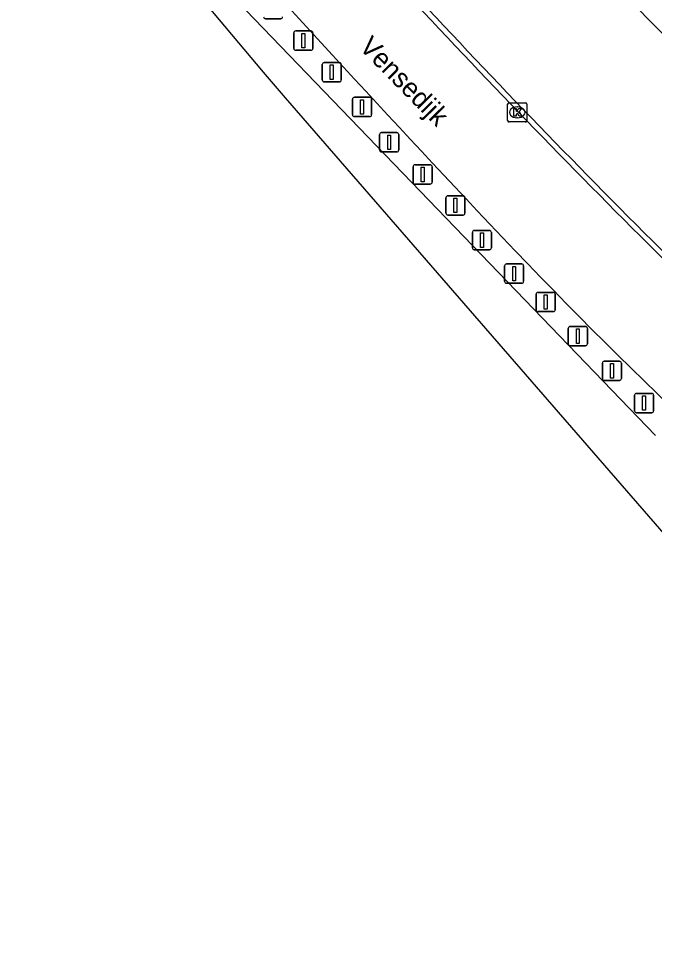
# Model space of a CAD drawing. Extents: x 156061 to 157804, y 383451 to 385640.
# Drawn here: x 156085.13 to 156118.12, y 385284.11 to 385332.59 of the extents above; entities that cross this region are included whole.
import ezdxf

# ---------------------------------------------------------------- set-up
doc = ezdxf.new("R2010")
doc.units = 0
for name, color, linetype in [('IMGEO_Afsluitpaal', 7, 'Continuous'), ('IMGEO_Berm_groen', 7, 'Continuous'), ('IMGEO_Groenvoorziening', 7, 'Continuous'), ('IMGEO_Kolk', 7, 'Continuous'), ('IMGEO_Openbare_ruimte_label', 7, 'Continuous'), ('IMGEO_Rijbaan_lokaal_gesloten', 7, 'Continuous'), ('IMGEO_Rijbaan_lokaal_open', 7, 'Continuous'), ('IMGEO_Waterloop', 7, 'Continuous')]:
    doc.layers.add(name, color=color, linetype=linetype)

msp = doc.modelspace()

# ---------------------------------------------------------------- linework, layer by layer
at = {"layer": 'IMGEO_Afsluitpaal'}
for p, q in [((156098.728, 385332.585), (156097.938, 385332.585)), ((156097.938, 385332.585), (156098.728, 385332.585)), ((156099.41, 385331.048), (156099.41, 385331.848)), ((156099.41, 385331.848), (156099.41, 385331.048)), ((156099.51, 385331.948), (156100.3, 385331.948)), ((156100.3, 385331.948), (156099.51, 385331.948)), ((156100.4, 385331.848), (156100.4, 385331.048)), ((156100.4, 385331.048), (156100.4, 385331.848)), ((156100.3, 385330.948), (156099.51, 385330.948)), ((156099.51, 385330.948), (156100.3, 385330.948)), ((156100.884, 385329.41), (156100.884, 385330.21)), ((156100.884, 385330.21), (156100.884, 385329.41)), ((156100.984, 385330.31), (156101.774, 385330.31)), ((156101.774, 385330.31), (156100.984, 385330.31)), ((156101.874, 385330.21), (156101.874, 385329.41)), ((156101.874, 385329.41), (156101.874, 385330.21)), ((156101.774, 385329.31), (156100.984, 385329.31)), ((156100.984, 385329.31), (156101.774, 385329.31)), ((156102.455, 385327.609), (156102.455, 385328.409)), ((156102.455, 385328.409), (156102.455, 385327.609)), ((156102.555, 385328.509), (156103.345, 385328.509)), ((156103.345, 385328.509), (156102.555, 385328.509)), ((156103.445, 385328.409), (156103.445, 385327.609)), ((156103.445, 385327.609), (156103.445, 385328.409)), ((156103.345, 385327.509), (156102.555, 385327.509)), ((156102.555, 385327.509), (156103.345, 385327.509)), ((156103.863, 385325.776), (156103.863, 385326.576)), ((156103.863, 385326.576), (156103.863, 385325.776)), ((156103.963, 385326.676), (156104.753, 385326.676)), ((156104.753, 385326.676), (156103.963, 385326.676)), ((156104.853, 385326.576), (156104.853, 385325.776)), ((156104.853, 385325.776), (156104.853, 385326.576)), ((156104.753, 385325.676), (156103.963, 385325.676)), ((156103.963, 385325.676), (156104.753, 385325.676)), ((156105.599, 385324.106), (156105.599, 385324.906)), ((156105.599, 385324.906), (156105.599, 385324.106)), ((156105.699, 385325.006), (156106.489, 385325.006)), ((156106.489, 385325.006), (156105.699, 385325.006)), ((156106.589, 385324.906), (156106.589, 385324.106)), ((156106.589, 385324.106), (156106.589, 385324.906)), ((156106.489, 385324.006), (156105.699, 385324.006)), ((156105.699, 385324.006), (156106.489, 385324.006)), ((156107.402, 385323.401), (156108.192, 385323.401)), ((156108.192, 385323.401), (156107.402, 385323.401)), ((156107.302, 385322.501), (156107.302, 385323.301)), ((156107.302, 385323.301), (156107.302, 385322.501)), ((156108.292, 385323.301), (156108.292, 385322.501)), ((156108.292, 385322.501), (156108.292, 385323.301)), ((156108.192, 385322.401), (156107.402, 385322.401)), ((156107.402, 385322.401), (156108.192, 385322.401)), ((156108.677, 385320.7), (156108.677, 385321.5)), ((156108.677, 385321.5), (156108.677, 385320.7)), ((156108.777, 385321.6), (156109.567, 385321.6)), ((156109.567, 385321.6), (156108.777, 385321.6)), ((156109.667, 385321.5), (156109.667, 385320.7)), ((156109.667, 385320.7), (156109.667, 385321.5)), ((156109.567, 385320.6), (156108.777, 385320.6)), ((156108.777, 385320.6), (156109.567, 385320.6)), ((156110.347, 385318.965), (156110.347, 385319.765)), ((156110.347, 385319.765), (156110.347, 385318.965)), ((156110.447, 385319.865), (156111.237, 385319.865)), ((156111.237, 385319.865), (156110.447, 385319.865)), ((156111.337, 385319.765), (156111.337, 385318.965)), ((156111.337, 385318.965), (156111.337, 385319.765)), ((156111.237, 385318.865), (156110.447, 385318.865)), ((156110.447, 385318.865), (156111.237, 385318.865)), ((156111.984, 385317.491), (156111.984, 385318.291)), ((156111.984, 385318.291), (156111.984, 385317.491)), ((156112.084, 385318.391), (156112.874, 385318.391)), ((156112.874, 385318.391), (156112.084, 385318.391)), ((156112.974, 385318.291), (156112.974, 385317.491)), ((156112.974, 385317.491), (156112.974, 385318.291)), ((156112.874, 385317.391), (156112.084, 385317.391)), ((156112.084, 385317.391), (156112.874, 385317.391)), ((156113.754, 385316.623), (156114.544, 385316.623)), ((156114.544, 385316.623), (156113.754, 385316.623)), ((156113.654, 385315.723), (156113.654, 385316.523)), ((156113.654, 385316.523), (156113.654, 385315.723)), ((156114.644, 385316.523), (156114.644, 385315.723)), ((156114.644, 385315.723), (156114.644, 385316.523)), ((156114.544, 385315.623), (156113.754, 385315.623)), ((156113.754, 385315.623), (156114.544, 385315.623)), ((156115.422, 385313.922), (156115.422, 385314.722)), ((156115.422, 385314.722), (156115.422, 385313.922)), ((156115.522, 385314.822), (156116.312, 385314.822)), ((156116.312, 385314.822), (156115.522, 385314.822)), ((156116.412, 385314.722), (156116.412, 385313.922)), ((156116.412, 385313.922), (156116.412, 385314.722)), ((156116.312, 385313.822), (156115.522, 385313.822)), ((156115.522, 385313.822), (156116.312, 385313.822)), ((156117.092, 385312.252), (156117.092, 385313.052)), ((156117.092, 385313.052), (156117.092, 385312.252)), ((156117.192, 385313.152), (156117.982, 385313.152)), ((156117.982, 385313.152), (156117.192, 385313.152)), ((156118.082, 385313.052), (156118.082, 385312.252)), ((156118.082, 385312.252), (156118.082, 385313.052)), ((156117.982, 385312.152), (156117.192, 385312.152)), ((156117.192, 385312.152), (156117.982, 385312.152))]:
    msp.add_line(p, q, dxfattribs=at)
for points in [[(156099.83, 385331.823), (156099.98, 385331.823), (156099.98, 385331.073), (156099.83, 385331.073), (156099.83, 385331.823)], [(156101.304, 385330.185), (156101.454, 385330.185), (156101.454, 385329.435), (156101.304, 385329.435), (156101.304, 385330.185)], [(156102.875, 385328.384), (156103.025, 385328.384), (156103.025, 385327.634), (156102.875, 385327.634), (156102.875, 385328.384)], [(156104.283, 385326.551), (156104.433, 385326.551), (156104.433, 385325.801), (156104.283, 385325.801), (156104.283, 385326.551)], [(156106.019, 385324.881), (156106.169, 385324.881), (156106.169, 385324.131), (156106.019, 385324.131), (156106.019, 385324.881)], [(156107.722, 385323.276), (156107.872, 385323.276), (156107.872, 385322.526), (156107.722, 385322.526), (156107.722, 385323.276)], [(156109.097, 385321.475), (156109.247, 385321.475), (156109.247, 385320.725), (156109.097, 385320.725), (156109.097, 385321.475)], [(156110.767, 385319.74), (156110.917, 385319.74), (156110.917, 385318.99), (156110.767, 385318.99), (156110.767, 385319.74)], [(156112.404, 385318.266), (156112.554, 385318.266), (156112.554, 385317.516), (156112.404, 385317.516), (156112.404, 385318.266)], [(156114.074, 385316.498), (156114.224, 385316.498), (156114.224, 385315.748), (156114.074, 385315.748), (156114.074, 385316.498)], [(156115.842, 385314.697), (156115.992, 385314.697), (156115.992, 385313.947), (156115.842, 385313.947), (156115.842, 385314.697)], [(156117.512, 385313.027), (156117.662, 385313.027), (156117.662, 385312.277), (156117.512, 385312.277), (156117.512, 385313.027)]]:
    msp.add_lwpolyline(points, dxfattribs=at)
for centre, start, end in [((156097.938, 385332.685), 180, 270), ((156097.938, 385332.685), 180, 270), ((156098.728, 385332.685), 270, 0), ((156098.728, 385332.685), 270, 0), ((156099.51, 385331.848), 90, 180), ((156099.51, 385331.848), 90, 180), ((156100.3, 385331.848), 0, 90), ((156100.3, 385331.848), 360, 90), ((156099.51, 385331.048), 180, 270), ((156099.51, 385331.048), 180, 270), ((156100.3, 385331.048), 270, 0), ((156100.3, 385331.048), 270, 0), ((156100.984, 385330.21), 90, 180), ((156100.984, 385330.21), 90, 180), ((156101.774, 385330.21), 0, 90), ((156101.774, 385330.21), 360, 90), ((156100.984, 385329.41), 180, 270), ((156100.984, 385329.41), 180, 270), ((156101.774, 385329.41), 270, 0), ((156101.774, 385329.41), 270, 0), ((156102.555, 385328.409), 90, 180), ((156102.555, 385328.409), 90, 180), ((156103.345, 385328.409), 0, 90), ((156103.345, 385328.409), 360, 90), ((156102.555, 385327.609), 180, 270), ((156102.555, 385327.609), 180, 270), ((156103.345, 385327.609), 270, 0), ((156103.345, 385327.609), 270, 0), ((156103.963, 385326.576), 90, 180), ((156103.963, 385326.576), 90, 180), ((156104.753, 385326.576), 0, 90), ((156104.753, 385326.576), 360, 90), ((156103.963, 385325.776), 180, 270), ((156103.963, 385325.776), 180, 270), ((156104.753, 385325.776), 270, 0), ((156104.753, 385325.776), 270, 0), ((156105.699, 385324.906), 90, 180), ((156105.699, 385324.906), 90, 180), ((156106.489, 385324.906), 0, 90), ((156106.489, 385324.906), 360, 90), ((156105.699, 385324.106), 180, 270), ((156105.699, 385324.106), 180, 270), ((156106.489, 385324.106), 270, 0), ((156106.489, 385324.106), 270, 0), ((156107.402, 385323.301), 90, 180), ((156107.402, 385323.301), 90, 180), ((156108.192, 385323.301), 0, 90), ((156108.192, 385323.301), 360, 90), ((156107.402, 385322.501), 180, 270), ((156107.402, 385322.501), 180, 270), ((156108.192, 385322.501), 270, 0), ((156108.192, 385322.501), 270, 0), ((156108.777, 385321.5), 90, 180), ((156108.777, 385321.5), 90, 180), ((156109.567, 385321.5), 0, 90), ((156109.567, 385321.5), 360, 90), ((156108.777, 385320.7), 180, 270), ((156108.777, 385320.7), 180, 270), ((156109.567, 385320.7), 270, 0), ((156109.567, 385320.7), 270, 0), ((156110.447, 385319.765), 90, 180), ((156110.447, 385319.765), 90, 180), ((156111.237, 385319.765), 0, 90), ((156111.237, 385319.765), 360, 90), ((156110.447, 385318.965), 180, 270), ((156110.447, 385318.965), 180, 270), ((156111.237, 385318.965), 270, 0), ((156111.237, 385318.965), 270, 0), ((156112.084, 385318.291), 90, 180), ((156112.084, 385318.291), 90, 180), ((156112.874, 385318.291), 0, 90), ((156112.874, 385318.291), 360, 90), ((156112.084, 385317.491), 180, 270), ((156112.084, 385317.491), 180, 270), ((156112.874, 385317.491), 270, 0), ((156112.874, 385317.491), 270, 0), ((156113.754, 385316.523), 90, 180), ((156113.754, 385316.523), 90, 180), ((156114.544, 385316.523), 0, 90), ((156114.544, 385316.523), 360, 90), ((156113.754, 385315.723), 180, 270), ((156113.754, 385315.723), 180, 270), ((156114.544, 385315.723), 270, 0), ((156114.544, 385315.723), 270, 0), ((156115.522, 385314.722), 90, 180), ((156115.522, 385314.722), 90, 180), ((156116.312, 385314.722), 0, 90), ((156116.312, 385314.722), 360, 90), ((156115.522, 385313.922), 180, 270), ((156115.522, 385313.922), 180, 270), ((156116.312, 385313.922), 270, 0), ((156116.312, 385313.922), 270, 0), ((156117.192, 385313.052), 90, 180), ((156117.192, 385313.052), 90, 180), ((156117.982, 385313.052), 0, 90), ((156117.982, 385313.052), 360, 90), ((156117.192, 385312.252), 180, 270), ((156117.192, 385312.252), 180, 270), ((156117.982, 385312.252), 270, 0), ((156117.982, 385312.252), 270, 0)]:
    msp.add_arc(centre, 0.1, start, end, dxfattribs=at)
at = {"layer": 'IMGEO_Berm_groen'}
msp.add_lwpolyline([(156118.185, 385310.964), (156091.934, 385338.209), (156086.7, 385344.464)], dxfattribs=at)
at = {"layer": 'IMGEO_Groenvoorziening'}
msp.add_lwpolyline([(156102.695, 385354.328), (156101.165, 385350.479), (156108.949, 385341.526), (156111.805, 385338.65), (156128.476, 385321.756), (156168.153, 385284.113)], dxfattribs=at)
at = {"layer": 'IMGEO_Kolk'}
for p, q in [((156110.58, 385328.228), (156111.432, 385328.228)), ((156110.505, 385327.302), (156110.505, 385328.154)), ((156110.993, 385328.008), (156111.018, 385328.008)), ((156111.506, 385328.154), (156111.506, 385327.302)), ((156111.432, 385327.228), (156110.58, 385327.228)), ((156111.016, 385327.448), (156110.991, 385327.448))]:
    msp.add_line(p, q, dxfattribs=at)
for points in [[(156110.58, 385328.228), (156111.432, 385328.228)], [(156110.505, 385327.302), (156110.505, 385328.154)], [(156110.826, 385327.928), (156110.949, 385327.928), (156110.949, 385327.777), (156111.079, 385327.928), (156111.243, 385327.928), (156111.097, 385327.777), (156111.25, 385327.528), (156111.098, 385327.528), (156111.013, 385327.692), (156110.949, 385327.625), (156110.949, 385327.528), (156110.826, 385327.528), (156110.826, 385327.928)], [(156111.506, 385328.154), (156111.506, 385327.302)], [(156111.432, 385327.228), (156110.58, 385327.228)]]:
    msp.add_lwpolyline(points, dxfattribs=at)
for centre, start, end in [((156110.582, 385328.152), 91.552, 178.448), ((156110.582, 385328.152), 91.552, 178.448), ((156111.43, 385328.152), 1.552, 88.448), ((156111.43, 385328.152), 1.552, 88.448), ((156110.582, 385327.304), 181.552, 268.448), ((156110.582, 385327.304), 181.552, 268.448), ((156111.43, 385327.304), 271.552, 358.448), ((156111.43, 385327.304), 271.552, 358.448)]:
    msp.add_arc(centre, 0.0765, start, end, dxfattribs=at)
for centre, major_axis, ratio, start_param, end_param in [((156110.992, 385327.728), (-0.387, 0.002), 0.722429, 4.712389, 7.853982), ((156111.017, 385327.728), (-0.39, 0.002), 0.717154, 1.570796, 4.712389)]:
    msp.add_ellipse(centre, major_axis=major_axis, ratio=ratio, start_param=start_param, end_param=end_param, dxfattribs=at)
at = {"layer": 'IMGEO_Rijbaan_lokaal_gesloten'}
for centre, radius, start, end in [((156881.513, 386049.075), 1060.48, 221.76934, 223.237566), ((156441.097, 385645.969), 458.462, 222.83854, 227.62493), ((156311.141, 385512.453), 277.354, 223.19188, 229.47603)]:
    msp.add_arc(centre, radius, start, end, dxfattribs=at)
at = {"layer": 'IMGEO_Rijbaan_lokaal_open'}
msp.add_arc((156444.762, 385648.913), 462.867, 222.80362, 227.53759, dxfattribs=at)
at = {"layer": 'IMGEO_Waterloop'}
msp.add_lwpolyline([(156124.228, 385299.412), (156098.982, 385328.474), (156097.839, 385329.812), (156091.895, 385336.876), (156090.784, 385337.539), (156085.132, 385343.571)], dxfattribs=at)

# ---------------------------------------------------------------- texts
at = {"layer": 'IMGEO_Openbare_ruimte_label'}
msp.add_text('Vensedijk', height=1, rotation=314.5948, dxfattribs=at).set_placement((156102.757, 385331.069))

doc.saveas('drawing.dxf')
